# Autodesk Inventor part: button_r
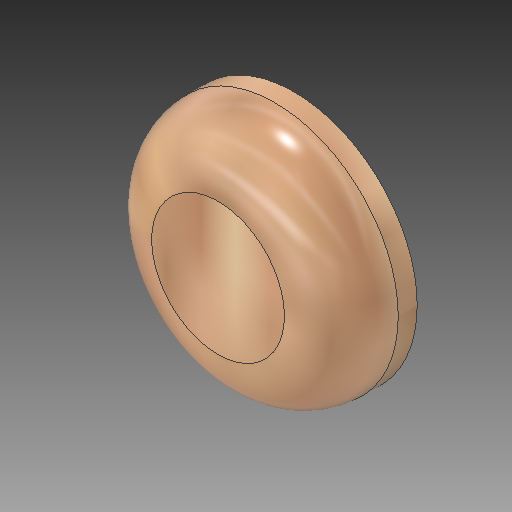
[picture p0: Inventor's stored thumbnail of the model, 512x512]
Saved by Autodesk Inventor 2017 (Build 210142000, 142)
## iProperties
Created: 2017-05
Part Number: button_r
Material: Generic
Document SubType Name: Modeling
Designer: alez_
Density: 1 g/cm^3
Appearance: Default
Author: alez_
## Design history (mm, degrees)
derived "button.ipt" dims "d0" = 11
feature "Solid1::button.ipt" dims "d0" = 11
tag "TaggingFeature1"
body "Solid1"
